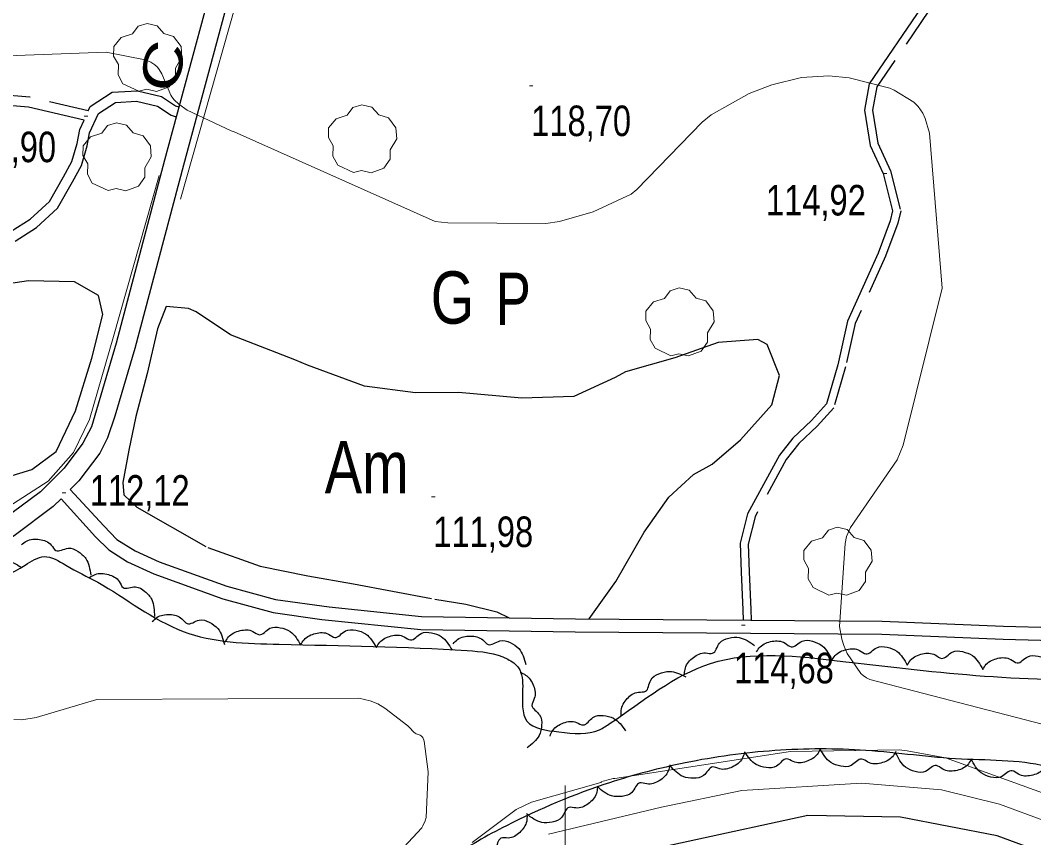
# Model space of a CAD drawing. Extents: x 483843 to 488449, y 4381269 to 4384483.
# Drawn here: x 484343.7 to 484634.4, y 4383510 to 4383744.3 of the extents above; entities that cross this region are included whole.
import ezdxf
from ezdxf.enums import TextEntityAlignment as Align

# ---------------------------------------------------------------- set-up
doc = ezdxf.new("R2010")
doc.units = 0
doc.header["$LTSCALE"] = 3.8
doc.linetypes.add('LONG_DASHED', pattern=[7.5, 6, -1.5])
doc.linetypes.add('MEDIUM_DASHED', pattern=[4.5, 3, -1.5])
for name, color, linetype, lineweight in [('1', 7, 'Continuous', 13), ('25', 7, 'LONG_DASHED', 25), ('27', 7, 'Continuous', 25), ('29', 7, 'Continuous', 13), ('36', 7, 'Continuous', 25), ('37', 7, 'Continuous', 25), ('38', 7, 'Continuous', 25), ('51', 7, 'Continuous', 13), ('7', 7, 'Continuous', 13), ('8', 7, 'Continuous', 25), ('9', 7, 'Continuous', 13)]:
    doc.layers.add(name, color=color, linetype=linetype, lineweight=lineweight)
doc.layers.add('31', color=7, linetype='Continuous')
doc.layers.add('5', color=7, linetype='Continuous')

msp = doc.modelspace()

# ---------------------------------------------------------------- linework, layer by layer
at = {"layer": '1'}
msp.add_line((484500, 4383525), (484500, 4383475), dxfattribs=at)
at = {"layer": '25'}
for points in [[(484274.54, 4383608.75), (484292.45, 4383604.39), (484326.41, 4383611.41), (484337.99, 4383612.75), (484347.07, 4383615.48), (484354, 4383620.65), (484359.61, 4383632.36), (484364.31, 4383647.45), (484367.45, 4383659.95), (484366.16, 4383665.4), (484359.29, 4383669.31), (484346.08, 4383669.6), (484334.83, 4383667.88), (484324.29, 4383666.16), (484315.1, 4383665.12), (484306.65, 4383661.22)], [(484506.9, 4383572.71), (484514.56, 4383583.46), (484522.66, 4383597.52), (484529.73, 4383607.55), (484536.8, 4383614.05), (484542.13, 4383617.01), (484550.32, 4383624.04), (484559.26, 4383634.03), (484561.44, 4383642.47), (484557.97, 4383651.36), (484555.25, 4383652.79), (484543.92, 4383651.96), (484531.42, 4383647.53), (484517.27, 4383643.51), (484514.31, 4383641.85), (484502.53, 4383636.43), (484487.55, 4383635.98), (484469.42, 4383637.55), (484457.07, 4383637.5), (484442.49, 4383639.44), (484426.13, 4383645.46), (484422.52, 4383646.94), (484404.01, 4383654.12), (484394.23, 4383660.71), (484392.03, 4383661.7), (484385.57, 4383662.23), (484383.11, 4383655.85), (484380.1, 4383643.05), (484376.89, 4383630.68), (484374.86, 4383621.11), (484373.14, 4383611.81), (484373.47, 4383608.22), (484377.17, 4383604.72), (484397.51, 4383593.18), (484412.55, 4383587.83), (484426.19, 4383585.04), (484439.28, 4383582.71), (484462.62, 4383578.33), (484471.54, 4383576.93), (484480.42, 4383574.69), (484483.9, 4383573.01)]]:
    msp.add_lwpolyline(points, dxfattribs=at)
at = {"layer": '27'}
for points in [[(484344.07, 4383593.94), (484345.51, 4383594.99), (484349.27, 4383595.46), (484352.61, 4383593.88), (484353.96, 4383592.33), (484357.46, 4383592.95), (484360.3, 4383592.04), (484362.53, 4383589.99), (484363.94, 4383585.24)], [(484100.18, 4383518.27), (484175.5, 4383526.23), (484263.69, 4383537.26), (484281.44, 4383543.39), (484323.7, 4383576.47), (484345.13, 4383588.11), (484350.64, 4383590.56), (484356.77, 4383588.11), (484365.95, 4383583.21), (484390.45, 4383569.12), (484418, 4383565.44), (484471.89, 4383563.61), (484483.53, 4383561.15), (484486.59, 4383558.7), (484487.81, 4383552.58), (484489.04, 4383543.39), (484498.22, 4383540.32), (484509.86, 4383540.94), (484512.92, 4383542.78), (484541.7, 4383559.93), (484579.67, 4383560.54), (484661.11, 4383555.64), (484694.18, 4383552.58), (484705.2, 4383543.39), (484711.33, 4383534.2), (484721.74, 4383509.08), (484724.19, 4383493.76), (484729.7, 4383491.31), (484743.17, 4383488.25), (484756.03, 4383490.09)], [(484324.81, 4383577.44), (484324.9, 4383579.21), (484326.88, 4383582.44), (484330.2, 4383584.06), (484332.25, 4383584.16), (484333.95, 4383587.28), (484336.44, 4383588.92), (484339.43, 4383589.39), (484344.03, 4383587.52)], [(484363.64, 4383584.6), (484365.21, 4383585.45), (484369, 4383585.42), (484372.1, 4383583.42), (484373.24, 4383581.71), (484376.8, 4383581.87), (484379.49, 4383580.59), (484381.43, 4383578.27), (484382.21, 4383573.37)], [(484381.61, 4383571.92), (484382.93, 4383573.11), (484386.62, 4383573.97), (484390.11, 4383572.75), (484391.62, 4383571.36), (484395.04, 4383572.35), (484397.96, 4383571.74), (484400.39, 4383569.94), (484402.3, 4383565.36)], [(484402.49, 4383566.05), (484403.45, 4383567.54), (484406.78, 4383569.35), (484410.47, 4383569.1), (484412.29, 4383568.16), (484415.33, 4383570.01), (484418.3, 4383570.19), (484421.12, 4383569.1), (484424.17, 4383565.19)], [(484424.18, 4383565.23), (484425.13, 4383566.73), (484428.45, 4383568.56), (484432.13, 4383568.33), (484433.96, 4383567.39), (484436.99, 4383569.26), (484439.97, 4383569.46), (484442.79, 4383568.39), (484445.86, 4383564.49)], [(484445.86, 4383564.5), (484446.82, 4383566), (484450.14, 4383567.83), (484453.82, 4383567.59), (484455.65, 4383566.66), (484458.68, 4383568.53), (484461.66, 4383568.72), (484464.48, 4383567.65), (484467.55, 4383563.75)], [(484467.88, 4383565.59), (484469.16, 4383566.82), (484472.83, 4383567.8), (484476.35, 4383566.68), (484477.9, 4383565.34), (484481.29, 4383566.42), (484484.23, 4383565.9), (484486.71, 4383564.18), (484488.75, 4383559.66)], [(484534.22, 4383556.88), (484534.47, 4383558.64), (484536.76, 4383561.67), (484540.22, 4383562.96), (484542.27, 4383562.85), (484544.27, 4383565.79), (484546.91, 4383567.19), (484549.93, 4383567.36), (484554.32, 4383565.05)], [(484554.87, 4383563.3), (484555.93, 4383564.72), (484559.39, 4383566.29), (484563.04, 4383565.77), (484564.8, 4383564.7), (484567.96, 4383566.33), (484570.94, 4383566.3), (484573.68, 4383565.01), (484576.44, 4383560.89)], [(484576.42, 4383560.73), (484577.41, 4383562.2), (484580.78, 4383563.95), (484584.45, 4383563.63), (484586.26, 4383562.65), (484589.33, 4383564.45), (484592.31, 4383564.57), (484595.11, 4383563.43), (484598.09, 4383559.46)], [(484598.09, 4383559.47), (484599.07, 4383560.95), (484602.44, 4383562.69), (484606.12, 4383562.37), (484607.92, 4383561.39), (484610.99, 4383563.19), (484613.98, 4383563.32), (484616.77, 4383562.17), (484619.75, 4383558.2)], [(484619.75, 4383558.22), (484620.74, 4383559.69), (484624.12, 4383561.42), (484627.79, 4383561.08), (484629.6, 4383560.1), (484632.67, 4383561.88), (484635.66, 4383562), (484638.45, 4383560.84), (484641.41, 4383556.86)], [(484487.06, 4383557.37), (484488.67, 4383556.62), (484490.91, 4383553.55), (484491.14, 4383549.87), (484490.45, 4383547.93), (484492.68, 4383545.17), (484493.26, 4383542.24), (484492.55, 4383539.3), (484489.07, 4383535.76)], [(484516.09, 4383544.74), (484516.05, 4383546.51), (484517.81, 4383549.87), (484521.01, 4383551.72), (484523.05, 4383551.95), (484524.53, 4383555.18), (484526.9, 4383557), (484529.85, 4383557.66), (484534.57, 4383556.12)], [(484495.66, 4383539.14), (484496.45, 4383540.73), (484499.56, 4383542.89), (484503.25, 4383543.04), (484505.17, 4383542.31), (484507.98, 4383544.48), (484510.92, 4383544.99), (484513.85, 4383544.22), (484517.31, 4383540.66)], [(484746.07, 4383463.39), (484731.66, 4383466.23), (484710.02, 4383482.88), (484695.11, 4383499.3), (484677.67, 4383512.8), (484658.52, 4383521.38), (484639.72, 4383529.93), (484613.7, 4383532.52), (484586.23, 4383535), (484560.15, 4383534.96), (484534.42, 4383531.45), (484512.75, 4383525.74), (484483.15, 4383513.44), (484467.12, 4383503.74), (484451.7, 4383489.36), (484436.59, 4383474.55), (484422.24, 4383456.04), (484409.9, 4383439.95), (484397.9, 4383426.91), (484376.97, 4383409.36), (484364.26, 4383397.36), (484342.02, 4383394.45), (484320.75, 4383398.94), (484298.45, 4383413.96), (484280.25, 4383425.55), (484249, 4383445.78), (484235.85, 4383460.09), (484215.96, 4383472.77), (484198.91, 4383469.03), (484171.82, 4383453.81), (484146.49, 4383453.37), (484110.53, 4383453.53), (484099.05, 4383450.9)], [(484551.43, 4383534.37), (484550.8, 4383532.71), (484547.91, 4383530.24), (484544.26, 4383529.73), (484542.28, 4383530.27), (484539.69, 4383527.83), (484536.82, 4383527.03), (484533.83, 4383527.51), (484530.04, 4383530.71)], [(484573.11, 4383535.44), (484572.27, 4383533.88), (484569.09, 4383531.82), (484565.39, 4383531.79), (484563.5, 4383532.59), (484560.62, 4383530.51), (484557.66, 4383530.1), (484554.77, 4383530.98), (484551.43, 4383534.64)], [(484594.8, 4383534.71), (484593.85, 4383533.21), (484590.52, 4383531.38), (484586.84, 4383531.62), (484585.01, 4383532.55), (484581.98, 4383530.68), (484579.01, 4383530.49), (484576.18, 4383531.56), (484573.11, 4383535.46)], [(484616.38, 4383532.27), (484615.35, 4383530.83), (484611.92, 4383529.2), (484608.26, 4383529.65), (484606.48, 4383530.69), (484603.36, 4383529), (484600.37, 4383528.97), (484597.61, 4383530.21), (484594.77, 4383534.28)], [(484529.98, 4383530.85), (484529.56, 4383529.13), (484526.98, 4383526.34), (484523.41, 4383525.4), (484521.38, 4383525.7), (484519.11, 4383522.97), (484516.34, 4383521.84), (484513.32, 4383521.97), (484509.18, 4383524.69)], [(484638.04, 4383530.98), (484637.03, 4383529.52), (484633.64, 4383527.82), (484629.97, 4383528.2), (484628.18, 4383529.2), (484625.08, 4383527.45), (484622.1, 4383527.37), (484619.32, 4383528.56), (484616.4, 4383532.57)], [(484509.26, 4383524.43), (484508.96, 4383522.68), (484506.59, 4383519.72), (484503.1, 4383518.52), (484501.05, 4383518.68), (484498.98, 4383515.79), (484496.3, 4383514.47), (484493.28, 4383514.38), (484488.95, 4383516.8)], [(484489.05, 4383516.5), (484488.96, 4383514.73), (484486.96, 4383511.5), (484483.63, 4383509.9), (484481.58, 4383509.82), (484479.86, 4383506.71), (484477.36, 4383505.08), (484474.37, 4383504.63), (484469.78, 4383506.52)]]:
    msp.add_spline(points, degree=3, dxfattribs=at)
at = {"layer": '29'}
for points in [[(484377.72, 4383723.96), (484373.18, 4383726.08), (484371.77, 4383728.62), (484371.87, 4383731.6), (484370.5, 4383734.01), (484370.54, 4383736.76), (484372.7, 4383739.36), (484375.89, 4383740.36), (484377.54, 4383742.55), (484380.11, 4383743.38), (484382.97, 4383742.73), (484384.92, 4383740.46), (484387.73, 4383739.64), (484389.86, 4383736.79), (484390.1, 4383733.66), (484388.22, 4383730.51), (484388.22, 4383727.83), (484386.4, 4383725.22), (484382.78, 4383723.88), (484380.01, 4383724.51)], [(484439.33, 4383700.64), (484434.79, 4383702.76), (484433.38, 4383705.3), (484433.48, 4383708.28), (484432.11, 4383710.69), (484432.15, 4383713.44), (484434.31, 4383716.04), (484437.5, 4383717.04), (484439.15, 4383719.23), (484441.72, 4383720.06), (484444.58, 4383719.41), (484446.53, 4383717.14), (484449.34, 4383716.32), (484451.47, 4383713.47), (484451.71, 4383710.34), (484449.83, 4383707.19), (484449.83, 4383704.51), (484448.01, 4383701.9), (484444.39, 4383700.56), (484441.62, 4383701.19)], [(484368.94, 4383695.48), (484364.4, 4383697.6), (484362.99, 4383700.14), (484363.09, 4383703.12), (484361.72, 4383705.53), (484361.76, 4383708.28), (484363.92, 4383710.88), (484367.11, 4383711.88), (484368.76, 4383714.07), (484371.33, 4383714.9), (484374.19, 4383714.25), (484376.14, 4383711.98), (484378.95, 4383711.16), (484381.08, 4383708.31), (484381.32, 4383705.18), (484379.44, 4383702.03), (484379.44, 4383699.35), (484377.62, 4383696.74), (484374, 4383695.4), (484371.23, 4383696.03)], [(484530.32, 4383648.14), (484525.78, 4383650.26), (484524.37, 4383652.8), (484524.47, 4383655.78), (484523.1, 4383658.19), (484523.14, 4383660.94), (484525.3, 4383663.54), (484528.49, 4383664.54), (484530.14, 4383666.73), (484532.71, 4383667.56), (484535.57, 4383666.91), (484537.52, 4383664.64), (484540.33, 4383663.82), (484542.46, 4383660.97), (484542.7, 4383657.84), (484540.82, 4383654.69), (484540.82, 4383652.01), (484539, 4383649.4), (484535.38, 4383648.06), (484532.61, 4383648.69)], [(484575.65, 4383579.54), (484571.11, 4383581.66), (484569.7, 4383584.2), (484569.8, 4383587.18), (484568.43, 4383589.59), (484568.47, 4383592.34), (484570.63, 4383594.94), (484573.82, 4383595.94), (484575.47, 4383598.13), (484578.04, 4383598.96), (484580.9, 4383598.31), (484582.85, 4383596.04), (484585.66, 4383595.22), (484587.79, 4383592.37), (484588.03, 4383589.24), (484586.15, 4383586.09), (484586.15, 4383583.41), (484584.33, 4383580.8), (484580.71, 4383579.46), (484577.94, 4383580.09)]]:
    msp.add_lwpolyline(points, close=True, dxfattribs=at)
at = {"layer": '36'}
for points in [[(484483.62, 4384135.07), (484480.51, 4384125.78), (484459.4, 4384066.54), (484450.92, 4384039.11), (484446.7, 4384023.41), (484440.33, 4383993.19), (484434.13, 4383944.43), (484428.99, 4383882.46), (484426.96, 4383858.28), (484425.86, 4383852.48), (484419.89, 4383830.41), (484404.46, 4383775.89), (484385.15, 4383704.18), (484371.21, 4383651.69), (484365.59, 4383632.66), (484364.18, 4383627.75), (484361.64, 4383623.03), (484356.29, 4383615.94), (484349.52, 4383609.16), (484338.85, 4383601.2)], [(484489.54, 4384135.06), (484485.82, 4384123.95), (484464.73, 4384064.76), (484456.32, 4384037.55), (484452.16, 4384022.11), (484445.88, 4383992.25), (484439.72, 4383943.85), (484434.59, 4383882), (484432.54, 4383857.52), (484431.34, 4383851.22), (484425.3, 4383828.91), (484409.87, 4383774.4), (484390.58, 4383702.73), (484376.62, 4383650.17), (484370.9, 4383630.79), (484368.78, 4383624.62), (484366.56, 4383620.22), (484360.54, 4383612.24), (484358.1, 4383609.8)], [(484355.45, 4383607.15), (484353.2, 4383604.9), (484341.95, 4383596.51), (484301.26, 4383572.73), (484269.92, 4383556.81), (484252.38, 4383549.34), (484239.72, 4383546.84), (484190.08, 4383539.15), (484154.17, 4383533.34), (484112.24, 4383526.64), (484099.2, 4383524.53)]]:
    msp.add_lwpolyline(points, dxfattribs=at)
at = {"layer": '37'}
for points in [[(484358.1, 4383609.8), (484367.68, 4383599.4), (484371.45, 4383595.48), (484376.7, 4383592.22), (484383.6, 4383589.04), (484402.95, 4383582.04), (484416.96, 4383578.25), (484432.28, 4383576.2), (484458.83, 4383573.36), (484502.94, 4383572.73), (484590.86, 4383572.07), (484625.69, 4383570.64), (484654.14, 4383569.88), (484686.28, 4383570.71), (484696.59, 4383569.94), (484701.94, 4383567.3), (484708.27, 4383560.8), (484737.22, 4383515.13)], [(484355.45, 4383607.15), (484365.28, 4383596.27), (484369.14, 4383592.47), (484374.49, 4383589.09), (484382.08, 4383585.61), (484401.82, 4383578.46), (484416.25, 4383574.56), (484430.25, 4383572.51), (484458.58, 4383569.62), (484502.9, 4383568.98), (484590.77, 4383568.32), (484625.56, 4383566.89), (484654.14, 4383566.13), (484686.19, 4383566.96), (484695.59, 4383566.26), (484699.7, 4383564.23), (484705.31, 4383558.47), (484734.06, 4383513.12)]]:
    msp.add_lwpolyline(points, dxfattribs=at)
at = {"layer": '38'}
for points in [[(484602.23, 4383748.02), (484587.21, 4383726.05), (484585.83, 4383718.52), (484587.5, 4383708.36), (484591.16, 4383700.4), (484593.87, 4383689.66), (484593.2, 4383686.83), (484589.71, 4383677.57), (484580.99, 4383658.08), (484578.2, 4383645.54), (484574.96, 4383634.34), (484570.65, 4383629.59), (484565.29, 4383624.48), (484561.44, 4383619.64), (484552.31, 4383602.82), (484550.22, 4383594.4), (484550.46, 4383586.08), (484550.97, 4383575.3), (484551.05, 4383572.37)], [(484362.05, 4383715.69), (484346.06, 4383719.41), (484325.37, 4383721.11)], [(484342.25, 4383680.98), (484348.42, 4383684.9), (484354.45, 4383690.46), (484358.75, 4383697.96), (484361.28, 4383702.68), (484362.89, 4383708.28), (484363.63, 4383712.04), (484366.14, 4383717.6), (484371.06, 4383720.75), (484377.08, 4383721.05), (484383.06, 4383719.67), (484386.97, 4383717.07), (484388.49, 4383716.56)]]:
    msp.add_lwpolyline(points, dxfattribs=at)
at = {"layer": '38', "linetype": 'MEDIUM_DASHED'}
for points in [[(484604.2, 4383746.86), (484589.36, 4383725.17), (484588.15, 4383718.5), (484589.7, 4383709.03), (484593.31, 4383701.16), (484596.22, 4383689.68), (484595.38, 4383686.16), (484591.82, 4383676.7), (484583.17, 4383657.36), (484580.41, 4383644.97), (484577.01, 4383633.2), (484572.28, 4383627.99), (484566.98, 4383622.94), (484563.35, 4383618.38), (484554.45, 4383601.98), (484552.51, 4383594.15), (484552.73, 4383586.17), (484553.24, 4383575.39), (484553.32, 4383572.35)], [(484363.24, 4383718.32), (484346.5, 4383722.22), (484325.81, 4383723.92)], [(484363.24, 4383718.32), (484363.81, 4383719.61), (484370.13, 4383723.66), (484377.34, 4383724.01), (484384.24, 4383722.42), (484388.28, 4383719.74), (484389.25, 4383719.42)], [(484139.42, 4383665.74), (484149.61, 4383663.91), (484162.03, 4383664.03), (484185.21, 4383664.62), (484214.65, 4383663.9), (484232.16, 4383664.15), (484246.93, 4383665.28), (484258.88, 4383665.06), (484270.01, 4383665.71), (484280.47, 4383666.6), (484294.1, 4383670.8), (484307.74, 4383677.66), (484315.73, 4383681.12), (484326.1, 4383682.01), (484331.84, 4383682.18), (484341.17, 4383683.79), (484346.61, 4383687.25), (484352.12, 4383692.32), (484356.17, 4383699.39), (484358.53, 4383703.8), (484360.02, 4383708.98), (484360.81, 4383712.94), (484362.05, 4383715.69)]]:
    msp.add_lwpolyline(points, dxfattribs=at)
at = {"layer": '51'}
for points in [[(484389.67, 4383693.04), (484412.38, 4383772.96), (484432.96, 4383848.65), (484436.93, 4383864.62), (484438.49, 4383890.95), (484445.61, 4383964.54), (484450.1, 4383998.92), (484453.76, 4384018.89), (484467.21, 4384059.78), (484480.93, 4384103.22), (484491.47, 4384135.06)], [(484099.22, 4383531.84), (484152.43, 4383540.61), (484213.14, 4383549), (484242.11, 4383554.64), (484258.94, 4383559.4), (484282.28, 4383571.32), (484322.87, 4383593.65), (484351.7, 4383612.15), (484359.02, 4383620.36), (484363.55, 4383629.89), (484370.47, 4383653.64), (484383.55, 4383699.81)]]:
    msp.add_lwpolyline(points, dxfattribs=at)
at = {"layer": '7'}
for p, q in [((484489.76, 4383725.45), (484490.76, 4383725.45)), ((484362.08, 4383716.82), (484363.08, 4383716.82)), ((484591.21, 4383700.4), (484592.21, 4383700.4)), ((484355.77, 4383608.81), (484356.77, 4383608.81)), ((484461.69, 4383607.67), (484462.69, 4383607.67)), ((484550.6, 4383570.91), (484551.6, 4383570.91))]:
    msp.add_line(p, q, dxfattribs=at)
at = {"layer": '8'}
msp.add_lwpolyline([(484649.33, 4383501.16), (484623.91, 4383510.53), (484596.2, 4383515.89), (484569.58, 4383516.37), (484500.95, 4383501.5)], dxfattribs=at)
at = {"layer": '9'}
for points in [[(484319.31, 4383733.34), (484368.39, 4383735.16), (484379.55, 4383732.9)], [(484379.55, 4383732.9), (484381.16, 4383732.26), (484382.3, 4383731.51), (484383.1, 4383730.8), (484383.59, 4383730.18), (484384.34, 4383728.96), (484386.91, 4383722.82), (484387.22, 4383722.33), (484387.92, 4383721.45), (484389.18, 4383720.2), (484391.64, 4383718.53), (484404.23, 4383712.58), (484404.53, 4383712.46), (484405.07, 4383712.33), (484462.7, 4383686.62), (484466.36, 4383686.21), (484494.5, 4383686.01), (484498.39, 4383686.65), (484508.04, 4383689.35), (484518.97, 4383694.43), (484520.53, 4383695.76), (484539.33, 4383715.04), (484541.88, 4383717.16), (484552.81, 4383723.25), (484559.22, 4383725.74), (484567.81, 4383727.86), (484575.62, 4383728.38), (484581.43, 4383727.82), (484593.06, 4383724.84), (484594.38, 4383724.23), (484599.98, 4383720.85), (484601.2, 4383719.61), (484602.57, 4383717.65), (484603.28, 4383716.16), (484604.48, 4383711.95), (484608.08, 4383667.53), (484596.92, 4383622.52), (484595.24, 4383618.28), (484581.8, 4383598.9), (484580.66, 4383596.36), (484580.29, 4383594.32), (484578.65, 4383570.57), (484579.33, 4383566.93), (484579.93, 4383565.04), (484580.9, 4383562.83), (484584.79, 4383557.06), (484585.43, 4383556.46), (484586.44, 4383555.79), (484587.34, 4383555.36), (484654.83, 4383537.88)], [(484435.74, 4383488), (484458.89, 4383512.86), (484459.21, 4383513.39), (484459.86, 4383514.82), (484460.12, 4383515.77), (484460.73, 4383528.84), (484459.6, 4383537.71), (484459.21, 4383538.74), (484458.75, 4383539.15), (484458.46, 4383539.34), (484457.31, 4383539.81), (484457.03, 4383539.95), (484456.61, 4383540.25), (484456.22, 4383540.61), (484455.64, 4383541.31), (484454.91, 4383542.05), (484448.33, 4383547.16), (484446.29, 4383548.32), (484444.12, 4383549.18), (484440.84, 4383549.98), (484365.66, 4383549.61), (484348.26, 4383544.41), (484344.2, 4383543.79), (484341.91, 4383543.83)], [(484656.52, 4383515.74), (484609.06, 4383532.85), (484598.03, 4383534.94), (484595.75, 4383535.14), (484564.58, 4383534.71), (484514.2, 4383526.97), (484513.8, 4383526.99), (484510.85, 4383526.21), (484510.44, 4383526.05), (484510.18, 4383525.84), (484490.32, 4383520.16), (484485.92, 4383518.06), (484473.36, 4383508.61)], [(484638.03, 4383514.66), (484624.55, 4383519.6), (484607.93, 4383523.7), (484584.98, 4383525.65), (484550.62, 4383523.55), (484527.6, 4383518.75), (484495.25, 4383510.99)]]:
    msp.add_lwpolyline(points, dxfattribs=at)

# ---------------------------------------------------------------- texts
at = {"layer": '31'}
for s, width, p in [('G', 0.8, (484467.69, 4383657.31)), ('P', 0.75, (484485.14, 4383656.94)), ('Am', 0.8, (484443.09, 4383608.74))]:
    msp.add_text(s, height=15, dxfattribs=dict(at, width=width)).set_placement(p, align=Align.CENTER)
at = {"layer": '5', "width": 1.35}
msp.add_text('C', height=10.99, rotation=75.964, dxfattribs=at).set_placement((484389.89, 4383729.79), align=Align.CENTER)
at = {"layer": '7', "width": 0.8}
for s, p in [('118,70', (484490.26, 4383711.08)), ('113,90', (484325.39, 4383703.6)), ('114,92', (484557.59, 4383688.33)), ('112,12', (484363.68, 4383605.17)), ('111,98', (484462.19, 4383593.3)), ('114,68', (484548.42, 4383554.24))]:
    msp.add_text(s, height=8.75, dxfattribs=at).set_placement(p)

doc.saveas('drawing.dxf')
